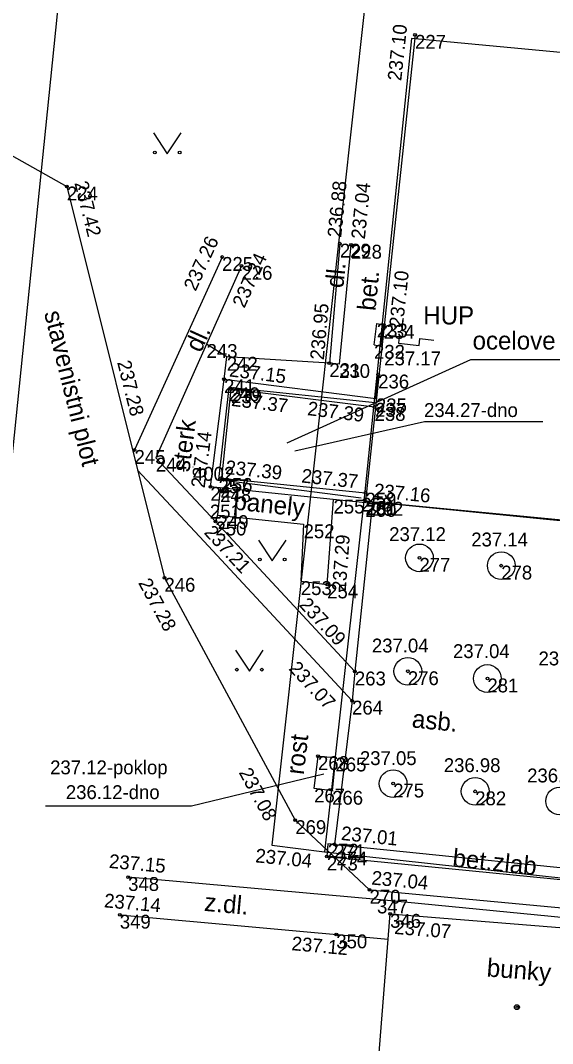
# Model space of a CAD drawing. Extents: x -596309 to -596099, y -1158697 to -1158513.
# Drawn here: x -596247.6 to -596228.41, y -1158676.95 to -1158640.06 of the extents above; entities that cross this region are included whole.
import ezdxf

# ---------------------------------------------------------------- set-up
doc = ezdxf.new("R2010")
doc.units = 0
for name, color, linetype in [('Vrstva 1', 7, 'Continuous'), ('Vrstva 10', 7, 'Continuous'), ('Vrstva 11', 7, 'Continuous'), ('Vrstva 2', 7, 'Continuous'), ('Vrstva 27', 7, 'Continuous'), ('Vrstva 3', 7, 'Continuous'), ('Vrstva 32', 7, 'Continuous'), ('Vrstva 36', 7, 'Continuous'), ('Vrstva 39', 7, 'Continuous'), ('Vrstva 40', 7, 'Continuous'), ('Vrstva 5', 7, 'Continuous'), ('Vrstva 51', 7, 'Continuous'), ('Vrstva 59', 7, 'Continuous'), ('Vrstva 6', 7, 'Continuous'), ('Vrstva 7', 7, 'Continuous'), ('Vrstva 9', 7, 'Continuous')]:
    doc.layers.add(name, color=color, linetype=linetype)

msp = doc.modelspace()

# ---------------------------------------------------------------- linework, layer by layer
at = {"layer": 'Vrstva 1'}
for p, q in [((-596244.17, -1158619.38), (-596252.171, -1158697)), ((-596235.17, -1158639.41), (-596238.54, -1158669.8)), ((-596210.4, -1158659.8), (-596235.22, -1158657.39)), ((-596238.54, -1158669.8), (-596236.63, -1158670.04))]:
    msp.add_line(p, q, dxfattribs=at)
msp.add_lwpolyline([(-596221.18, -1158580.18), (-596227.49, -1158641.27), (-596233.5, -1158640.71), (-596235.22, -1158657.39), (-596236.63, -1158670.04), (-596220.14, -1158671.86), (-596212.02, -1158672.68), (-596210.4, -1158659.8), (-596209.78, -1158653.62)], dxfattribs=at)
at = {"layer": 'Vrstva 10'}
msp.add_line((-596235.64, -1158664.59), (-596235.64, -1158664.59), dxfattribs=at)
msp.add_lwpolyline([(-596234.91, -1158657.42), (-596235.54, -1158663.54), (-596235.64, -1158664.59), (-596236.28, -1158669.77), (-596224.72, -1158670.95), (-596219.27, -1158671.44), (-596219.31, -1158671.81), (-596217.76, -1158672.7), (-596216.62, -1158673.4), (-596215.57, -1158674.26), (-596214.79, -1158675.05), (-596213.89, -1158676.38), (-596213.06, -1158678.46), (-596212.57, -1158681.01), (-596212.72, -1158682.76)], dxfattribs=at)
at = {"layer": 'Vrstva 11'}
for p, q in [((-596236.08, -1158648.11), (-596236.46, -1158652.42)), ((-596240.33, -1158648.59), (-596243.535, -1158655.65)), ((-596240.49, -1158657.9), (-596240.57, -1158658.13)), ((-596244.02, -1158672.31), (-596234.342, -1158673.19))]:
    msp.add_line(p, q, dxfattribs=at)
for points in [[(-596235.68, -1158648.15), (-596236.11, -1158652.45), (-596236.46, -1158652.42), (-596240.16, -1158652.19)], [(-596239.63, -1158648.91), (-596240.89, -1158651.73), (-596242.72, -1158655.83)], [(-596240.26, -1158653), (-596240.16, -1158652.19), (-596240.89, -1158651.73)], [(-596234.83, -1158654), (-596240.01, -1158653.36), (-596240.35, -1158656.56), (-596235.16, -1158657.09)], [(-596242.72, -1158655.83), (-596240.57, -1158658.13), (-596235.54, -1158663.54)], [(-596243.378, -1158656.281), (-596241.147, -1158658.667), (-596235.64, -1158664.59)], [(-596240.4, -1158656.93), (-596240.49, -1158657.9), (-596237.39, -1158658.23), (-596237.49, -1158660.28), (-596236.54, -1158660.4), (-596236.31, -1158657.34)], [(-596236.28, -1158669.77), (-596236.52, -1158669.75), (-596236.55, -1158670.21), (-596224.69, -1158671.37), (-596224.58, -1158672.5), (-596224.05, -1158672.59), (-596223.71, -1158671.47), (-596219.31, -1158671.81)], [(-596216.62, -1158673.4), (-596224.28, -1158672.78), (-596234.74, -1158671.76), (-596243.72, -1158670.95)]]:
    msp.add_lwpolyline(points, dxfattribs=at)
msp.add_lwpolyline([(-596236.24, -1158666.64), (-596236.36, -1158667.84), (-596237.01, -1158667.76), (-596236.87, -1158666.59)], close=True, dxfattribs=at)
at = {"layer": 'Vrstva 2'}
for points in [[(-596228.759, -1158654.536), (-596233.023, -1158654.536), (-596237.704, -1158655.594)], [(-596246.703, -1158668.386), (-596241.434, -1158668.386), (-596236.661, -1158667.229)]]:
    msp.add_lwpolyline(points, dxfattribs=at)
for centre in [(-596233.37, -1158640.58), (-596245.93, -1158646.05), (-596236.08, -1158648.11), (-596235.68, -1158648.15), (-596240.33, -1158648.59), (-596239.63, -1158648.91), (-596234.5, -1158651.04), (-596236.46, -1158652.42), (-596234.7, -1158652.83), (-596240.26, -1158653), (-596240.01, -1158653.36), (-596234.83, -1158654), (-596243.49, -1158655.55), (-596240.35, -1158656.56), (-596240.75, -1158656.88), (-596235.16, -1158657.09), (-596235.16, -1158657.39), (-596240.57, -1158658.13), (-596233.21, -1158659.44), (-596230.26, -1158659.72), (-596242.41, -1158660.16), (-596236.54, -1158660.4), (-596235.54, -1158663.54), (-596233.63, -1158663.53), (-596230.76, -1158663.79), (-596235.64, -1158664.59), (-596236.87, -1158666.59), (-596234.16, -1158667.58), (-596231.2, -1158667.86), (-596237.69, -1158668.9), (-596236.28, -1158669.77), (-596236.55, -1158670.21), (-596243.72, -1158670.95), (-596235.01, -1158671.41), (-596244.02, -1158672.31), (-596234.27, -1158672.28), (-596236.21, -1158673.02)]:
    msp.add_circle(centre, 0.05, dxfattribs=at)
at = {"layer": 'Vrstva 27'}
for centre in [(-596233.21, -1158659.44), (-596230.26, -1158659.72), (-596233.63, -1158663.53), (-596230.76, -1158663.79), (-596234.16, -1158667.58), (-596231.2, -1158667.86), (-596228.15, -1158668.21)]:
    msp.add_circle(centre, 0.5, dxfattribs=at)
at = {"layer": 'Vrstva 3'}
for p, q in [((-596233.37, -1158640.58), (-596233.369, -1158640.58)), ((-596245.93, -1158646.05), (-596245.929, -1158646.05)), ((-596236.08, -1158648.11), (-596236.079, -1158648.11)), ((-596235.68, -1158648.15), (-596235.679, -1158648.15)), ((-596240.33, -1158648.59), (-596240.329, -1158648.59)), ((-596239.63, -1158648.91), (-596239.629, -1158648.91)), ((-596234.75, -1158650.99), (-596234.749, -1158650.99)), ((-596234.5, -1158651.04), (-596234.499, -1158651.04)), ((-596240.89, -1158651.73), (-596240.889, -1158651.73)), ((-596234.85, -1158651.76), (-596234.849, -1158651.76)), ((-596240.16, -1158652.19), (-596240.159, -1158652.19)), ((-596236.46, -1158652.42), (-596236.459, -1158652.42)), ((-596236.11, -1158652.45), (-596236.109, -1158652.45)), ((-596234.7, -1158652.83), (-596234.699, -1158652.83)), ((-596240.26, -1158653), (-596240.259, -1158653)), ((-596240.09, -1158653.29), (-596240.089, -1158653.29)), ((-596240.01, -1158653.36), (-596240.009, -1158653.36)), ((-596234.83, -1158654), (-596234.829, -1158654)), ((-596234.81, -1158653.85), (-596234.809, -1158653.85)), ((-596234.78, -1158653.69), (-596234.779, -1158653.69)), ((-596243.49, -1158655.55), (-596243.489, -1158655.55)), ((-596242.72, -1158655.83), (-596242.719, -1158655.83)), ((-596241.38, -1158656.16), (-596241.379, -1158656.16)), ((-596240.46, -1158656.61), (-596240.459, -1158656.61)), ((-596240.35, -1158656.56), (-596240.349, -1158656.56)), ((-596240.75, -1158656.88), (-596240.749, -1158656.88)), ((-596240.4, -1158656.93), (-596240.399, -1158656.93)), ((-596236.31, -1158657.34), (-596236.309, -1158657.34)), ((-596235.31, -1158657.27), (-596235.309, -1158657.27)), ((-596235.16, -1158657.09), (-596235.159, -1158657.09)), ((-596240.77, -1158657.52), (-596240.769, -1158657.52)), ((-596235.16, -1158657.39), (-596235.159, -1158657.39)), ((-596235.16, -1158657.46), (-596235.159, -1158657.46)), ((-596234.91, -1158657.42), (-596234.909, -1158657.42)), ((-596240.49, -1158657.9), (-596240.489, -1158657.9)), ((-596240.57, -1158658.13), (-596240.569, -1158658.13)), ((-596237.39, -1158658.23), (-596237.389, -1158658.23)), ((-596233.21, -1158659.44), (-596233.209, -1158659.44)), ((-596230.26, -1158659.72), (-596230.259, -1158659.72)), ((-596242.41, -1158660.16), (-596242.409, -1158660.16)), ((-596237.49, -1158660.28), (-596237.489, -1158660.28)), ((-596236.54, -1158660.4), (-596236.539, -1158660.4)), ((-596235.54, -1158663.54), (-596235.539, -1158663.54)), ((-596233.63, -1158663.53), (-596233.629, -1158663.53)), ((-596230.76, -1158663.79), (-596230.759, -1158663.79)), ((-596235.64, -1158664.59), (-596235.639, -1158664.59)), ((-596236.87, -1158666.59), (-596236.869, -1158666.59)), ((-596236.24, -1158666.64), (-596236.239, -1158666.64)), ((-596234.16, -1158667.58), (-596234.159, -1158667.58)), ((-596237.01, -1158667.76), (-596237.009, -1158667.76)), ((-596236.36, -1158667.84), (-596236.359, -1158667.84)), ((-596231.2, -1158667.86), (-596231.199, -1158667.86)), ((-596237.69, -1158668.9), (-596237.689, -1158668.9)), ((-596236.52, -1158669.75), (-596236.519, -1158669.75)), ((-596236.28, -1158669.77), (-596236.279, -1158669.77)), ((-596236.55, -1158670.21), (-596236.549, -1158670.21)), ((-596236.21, -1158670.03), (-596236.209, -1158670.03)), ((-596243.72, -1158670.95), (-596243.719, -1158670.95)), ((-596235.01, -1158671.41), (-596235.009, -1158671.41)), ((-596234.74, -1158671.76), (-596234.739, -1158671.76)), ((-596244.02, -1158672.31), (-596244.019, -1158672.31)), ((-596234.27, -1158672.28), (-596234.269, -1158672.28)), ((-596236.21, -1158673.02), (-596236.209, -1158673.02))]:
    msp.add_line(p, q, dxfattribs=at)
at = {"layer": 'Vrstva 32'}
msp.add_lwpolyline([(-596234.435, -1158651.401), (-596233.938, -1158651.454), (-596233.964, -1158651.702), (-596233.219, -1158651.783), (-596233.192, -1158651.534), (-596232.695, -1158651.587)], dxfattribs=at)
at = {"layer": 'Vrstva 36'}
for points in [[(-596242.81, -1158644.118), (-596242.31, -1158644.868), (-596241.81, -1158644.118)], [(-596239.022, -1158658.798), (-596238.522, -1158659.548), (-596238.022, -1158658.798)], [(-596239.844, -1158662.771), (-596239.344, -1158663.521), (-596238.844, -1158662.771)]]:
    msp.add_lwpolyline(points, dxfattribs=at)
for centre in [(-596242.76, -1158644.818), (-596241.86, -1158644.818), (-596238.972, -1158659.498), (-596238.073, -1158659.498), (-596239.795, -1158663.471), (-596238.895, -1158663.471)]:
    msp.add_circle(centre, 0.05, dxfattribs=at)
at = {"layer": 'Vrstva 39'}
for radius in [0.09, 0.0398]:
    msp.add_circle((-596229.695, -1158675.642), radius, dxfattribs=at)
at = {"layer": 'Vrstva 40'}
msp.add_lwpolyline([(-596220.447, -1158652.295), (-596231.373, -1158652.295), (-596237.993, -1158655.304)], dxfattribs=at)
at = {"layer": 'Vrstva 5'}
msp.add_lwpolyline([(-596233.37, -1158640.58), (-596235.16, -1158657.39), (-596209.99, -1158659.89)], dxfattribs=at)
msp.add_lwpolyline([(-596234.27, -1158672.28), (-596223.97, -1158673.1), (-596224.452, -1158679.161), (-596234.752, -1158678.341)], close=True, dxfattribs=at)
at = {"layer": 'Vrstva 51'}
for points in [[(-596234.85, -1158651.76), (-596234.75, -1158650.99), (-596234.5, -1158651.04)], [(-596234.85, -1158651.76), (-596234.6, -1158651.81), (-596234.5, -1158651.04)]]:
    msp.add_lwpolyline(points, dxfattribs=at)
at = {"layer": 'Vrstva 6'}
msp.add_line((-596234.78, -1158653.69), (-596234.7, -1158652.83), dxfattribs=at)
at = {"layer": 'Vrstva 7'}
for points in [[(-596278.232, -1158646.344), (-596264.01, -1158641.67), (-596260.07, -1158635.97), (-596256.51, -1158635.49), (-596257.17, -1158642.42), (-596249.77, -1158643.89), (-596245.93, -1158646.05), (-596242.41, -1158660.16), (-596237.69, -1158668.9), (-596235.01, -1158671.41), (-596218.43, -1158672.96), (-596214.81, -1158675.09)], [(-596235.16, -1158657.39), (-596235.16, -1158657.46), (-596240.75, -1158656.88), (-596240.26, -1158653), (-596234.78, -1158653.69)]]:
    msp.add_lwpolyline(points, dxfattribs=at)
at = {"layer": 'Vrstva 9'}
msp.add_lwpolyline([(-596234.81, -1158653.85), (-596240.09, -1158653.29), (-596240.46, -1158656.61), (-596235.31, -1158657.27)], dxfattribs=at)

# ---------------------------------------------------------------- texts
at = {"layer": 'Vrstva 2'}
for s, rotation, p in [('237.10', 83.9218, (-596233.867, -1158642.257)), ('237.42', 284.0076, (-596245.66, -1158645.919)), ('236.88', 84.2894, (-596236.035, -1158647.905)), ('237.04', 84.2894, (-596235.18, -1158647.964)), ('237.26', 65.5809, (-596241.284, -1158649.85)), ('237.24', 65.9245, (-596239.527, -1158650.461)), ('237.10', 83.9218, (-596233.808, -1158651.141)), ('236.95', 84.9614, (-596236.66, -1158652.317)), ('237.28', 284.0076, (-596244.118, -1158652.385)), ('237.15', 352.8235, (-596240.087, -1158652.893)), ('237.37', 352.9567, (-596240.014, -1158653.958)), ('237.39', 352.9567, (-596237.273, -1158654.289)), ('237.14', 82.8023, (-596240.96, -1158656.937)), ('237.39', 354.1692, (-596240.229, -1158656.413)), ('237.37', 353.9218, (-596237.484, -1158656.719)), ('237.16', 354.3277, (-596234.873, -1158657.248)), ('237.21', 312.9154, (-596241.008, -1158658.546)), ('237.29', 85.7015, (-596235.871, -1158660.658)), ('237.28', 298.3711, (-596243.365, -1158660.342)), ('237.09', 312.9154, (-596237.578, -1158661.155)), ('237.07', 312.9154, (-596237.952, -1158663.451)), ('237.08', 298.3711, (-596239.738, -1158667.177)), ('237.01', 354.1717, (-596236.056, -1158669.61)), ('237.15', 354.8458, (-596244.426, -1158670.618)), ('237.04', 354.4138, (-596239.147, -1158670.417)), ('237.04', 354.6592, (-596234.954, -1158671.218)), ('237.14', 354.8458, (-596244.601, -1158672.039)), ('237.07', 355.4482, (-596234.131, -1158673)), ('237.12', 354.8056, (-596237.838, -1158673.585))]:
    msp.add_text(s, height=0.5, rotation=rotation, dxfattribs=at).set_placement(p)
for s, p in [('237.17', (-596234.482, -1158652.497)), ('234.27-dno', (-596233.045, -1158654.36)), ('237.12', (-596234.302, -1158658.834)), ('237.14', (-596231.342, -1158659.027)), ('237.04', (-596234.927, -1158662.852)), ('237.04', (-596232, -1158663.054)), ('237.05', (-596228.916, -1158663.316)), ('237.05', (-596235.358, -1158666.912)), ('237.12-poklop', (-596246.533, -1158667.245)), ('236.98', (-596232.333, -1158667.167)), ('236.98', (-596229.326, -1158667.537)), ('236.12-dno', (-596245.966, -1158668.138))]:
    msp.add_text(s, height=0.5, dxfattribs=at).set_placement(p)
at = {"layer": 'Vrstva 40'}
for s, rotation, p in [('dl.', 84.2894, (-596235.959, -1158649.728)), ('bet.', 84.2894, (-596234.8, -1158650.55)), ('stavenistni plot', 284.0076, (-596246.754, -1158650.604)), ('dl.', 65.5809, (-596241.1, -1158652.068)), ('sterk', 82.8023, (-596241.51, -1158656.364)), ('panely', 354.0764, (-596239.94, -1158657.693)), ('asb.', 354.3277, (-596233.503, -1158665.553)), ('rost', 83.1765, (-596237.388, -1158667.281)), ('bet.zlab', 354.1717, (-596232.041, -1158670.57)), ('z.dl.', 354.8458, (-596240.992, -1158672.167)), ('bunky', 355.4482, (-596230.8, -1158674.532))]:
    msp.add_text(s, height=0.65, rotation=rotation, dxfattribs=at).set_placement(p)
for s, p in [('HUP', (-596233.074, -1158651.021)), ('ocelove plech. platy', (-596231.295, -1158651.926))]:
    msp.add_text(s, height=0.65, dxfattribs=at).set_placement(p)
at = {"layer": 'Vrstva 59'}
for s, p in [('227', (-596233.37, -1158641.08)), ('224', (-596245.93, -1158646.55)), ('229', (-596236.08, -1158648.61)), ('228', (-596235.68, -1158648.65)), ('225', (-596240.33, -1158649.09)), ('226', (-596239.63, -1158649.41)), ('233', (-596234.75, -1158651.49)), ('234', (-596234.5, -1158651.54)), ('243', (-596240.89, -1158652.23)), ('232', (-596234.85, -1158652.26)), ('242', (-596240.16, -1158652.69)), ('231', (-596236.46, -1158652.92)), ('230', (-596236.11, -1158652.95)), ('236', (-596234.7, -1158653.33)), ('241', (-596240.26, -1158653.5)), ('240', (-596240.09, -1158653.79)), ('239', (-596240.01, -1158653.86)), ('238', (-596234.83, -1158654.5)), ('237', (-596234.81, -1158654.35)), ('235', (-596234.78, -1158654.19)), ('245', (-596243.49, -1158656.05)), ('244', (-596242.72, -1158656.33)), ('4002', (-596241.38, -1158656.66)), ('257', (-596240.46, -1158657.11)), ('256', (-596240.35, -1158657.06)), ('247', (-596240.75, -1158657.38)), ('248', (-596240.4, -1158657.43)), ('255', (-596236.31, -1158657.84)), ('258', (-596235.31, -1158657.77)), ('259', (-596235.16, -1158657.59)), ('251', (-596240.77, -1158658.02)), ('261', (-596235.16, -1158657.89)), ('260', (-596235.16, -1158657.96)), ('262', (-596234.91, -1158657.92)), ('249', (-596240.49, -1158658.4)), ('250', (-596240.57, -1158658.63)), ('252', (-596237.39, -1158658.73)), ('277', (-596233.21, -1158659.94)), ('278', (-596230.26, -1158660.22)), ('246', (-596242.41, -1158660.66)), ('253', (-596237.49, -1158660.78)), ('254', (-596236.54, -1158660.9)), ('263', (-596235.54, -1158664.04)), ('276', (-596233.63, -1158664.03)), ('281', (-596230.76, -1158664.29)), ('264', (-596235.64, -1158665.09)), ('268', (-596236.87, -1158667.09)), ('265', (-596236.24, -1158667.14)), ('275', (-596234.16, -1158668.08)), ('267', (-596237.01, -1158668.26)), ('266', (-596236.36, -1158668.34)), ('282', (-596231.2, -1158668.36)), ('269', (-596237.69, -1158669.4)), ('272', (-596236.52, -1158670.25)), ('271', (-596236.28, -1158670.27)), ('273', (-596236.55, -1158670.71)), ('274', (-596236.21, -1158670.53)), ('348', (-596243.72, -1158671.45)), ('270', (-596235.01, -1158671.91)), ('347', (-596234.74, -1158672.26)), ('349', (-596244.02, -1158672.81)), ('346', (-596234.27, -1158672.78)), ('350', (-596236.21, -1158673.52))]:
    msp.add_text(s, height=0.5, dxfattribs=at).set_placement(p)

doc.saveas('drawing.dxf')
